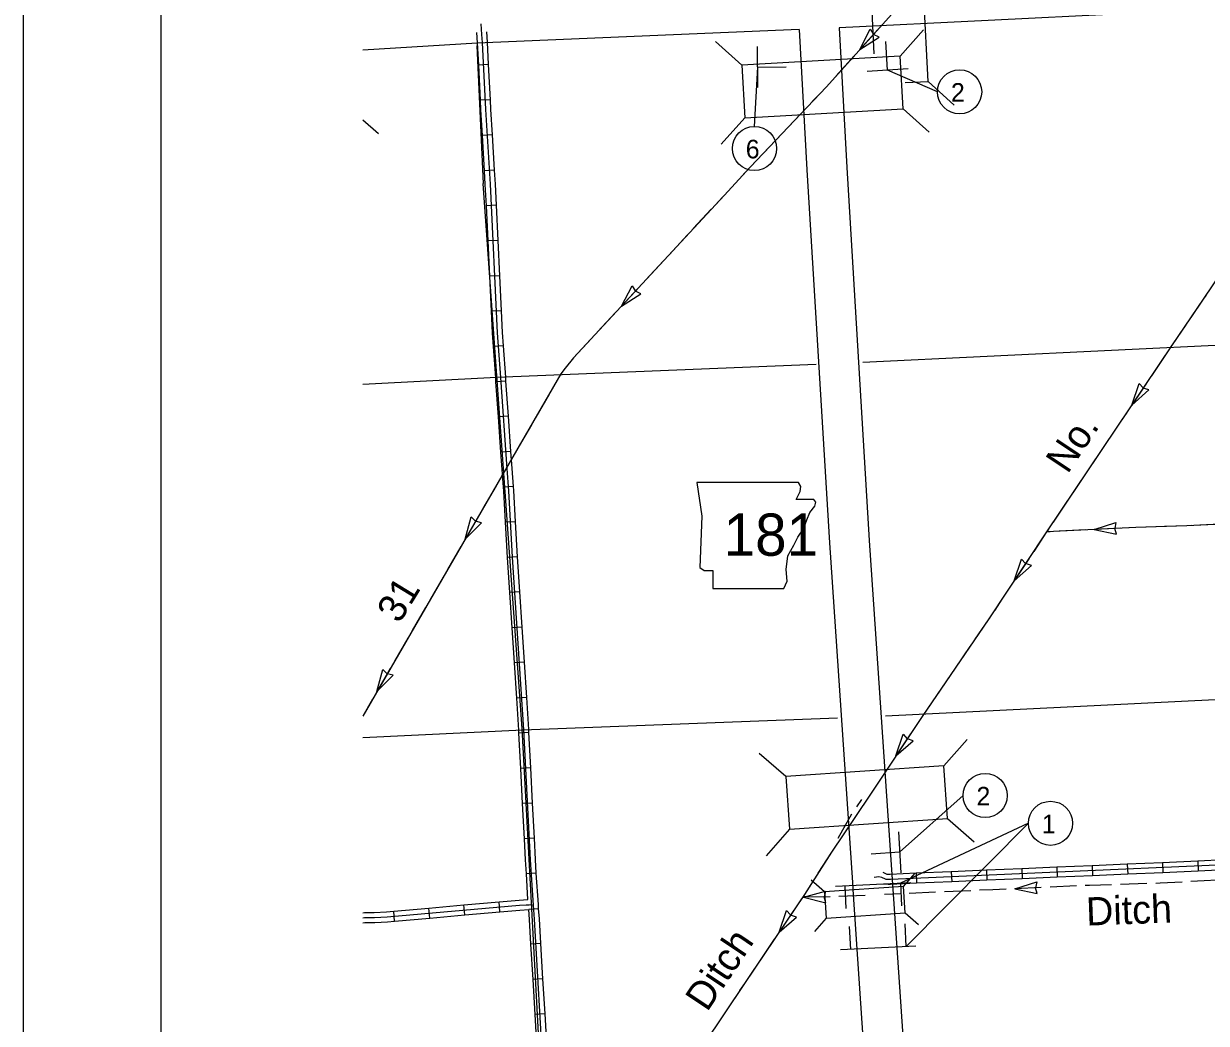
# Model space of a CAD drawing. Extents: x 9792 to 14027, y 9583 to 10649.
# Drawn here: x 9792 to 10326, y 9947 to 10398 of the extents above; entities that cross this region are included whole.
import ezdxf

# ---------------------------------------------------------------- set-up
doc = ezdxf.new("R2010")
doc.units = 0
for name, color, linetype in [('Default', 7, 'Continuous'), ('R_Border', 7, 'Continuous'), ('R_Border Notes', 7, 'Continuous'), ('R_MOT', 7, 'Continuous'), ('R_No Plot', 7, 'Continuous')]:
    doc.layers.add(name, color=color, linetype=linetype)

msp = doc.modelspace()

# ---------------------------------------------------------------- linework, layer by layer
at = {"layer": 'Default'}
for p, q in [((10200.73, 10372.15), (10197.23, 10443.68)), ((10173.39, 10442.51), (10176.22, 10384.58)), ((10169.89, 10386.55), (10174.59, 10395.76)), ((10174.59, 10395.76), (10176.09, 10393.45)), ((10188.07, 10383.64), (10198.67, 10395.51)), ((10116.57, 10379.59), (10104.7, 10390.19)), ((10169.89, 10386.55), (10178.57, 10392.18)), ((10178.57, 10392.18), (10176.12, 10393.43)), ((10002.25, 10379.77), (9997.74, 10379.55)), ((10190.3, 10371.64), (10200.73, 10372.15)), ((10200.73, 10372.15), (10212.52, 10361.46)), ((10003.04, 10363.88), (9998.53, 10363.65)), ((10189.42, 10359.8), (10201.29, 10349.2)), ((9945.36, 10354.85), (9952.44, 10348.59)), ((10117.92, 10355.76), (10107.32, 10343.88)), ((10003.94, 10348.01), (9999.43, 10347.74)), ((10004.89, 10332.12), (10000.38, 10331.85)), ((10005.74, 10316.21), (10001.22, 10315.98)), ((10006.52, 10300.31), (10002, 10300.09)), ((10007.3, 10284.41), (10002.78, 10284.19)), ((10062.2, 10270.68), (10067.04, 10279.83)), ((10067.04, 10279.83), (10068.5, 10277.49)), ((10062.2, 10270.68), (10070.96, 10276.18)), ((10070.96, 10276.18), (10068.53, 10277.47)), ((10008.08, 10268.52), (10003.57, 10268.3)), ((10008.98, 10252.67), (10004.47, 10252.36)), ((10010.08, 10236.8), (10005.56, 10236.49)), ((10292.71, 10225.96), (10296.05, 10235.75)), ((10296.05, 10235.75), (10297.86, 10233.68)), ((10292.71, 10225.96), (10300.5, 10232.77)), ((10300.5, 10232.77), (10297.89, 10233.66)), ((10011.17, 10220.92), (10006.66, 10220.61)), ((10012.27, 10205.04), (10007.76, 10204.73)), ((10013.46, 10189.2), (10008.95, 10188.84)), ((9991.66, 10165.43), (9994.34, 10175.42)), ((9991.66, 10165.43), (9998.98, 10172.73)), ((9994.34, 10175.42), (9996.29, 10173.47)), ((9998.98, 10172.73), (9996.32, 10173.45)), ((10014.42, 10173.26), (10009.9, 10173)), ((10275.76, 10169.73), (10285.6, 10172.92)), ((10285.6, 10172.92), (10285.02, 10170.22)), ((10275.76, 10169.73), (10285.87, 10167.57)), ((10285.87, 10167.57), (10285.03, 10170.19)), ((10015.33, 10157.37), (10010.82, 10157.11)), ((10239.62, 10146.59), (10242.92, 10156.4)), ((10242.92, 10156.4), (10244.74, 10154.33)), ((10239.62, 10146.59), (10247.38, 10153.44)), ((10247.38, 10153.44), (10244.77, 10154.31)), ((10016.36, 10141.51), (10011.85, 10141.21)), ((10017.39, 10125.63), (10012.88, 10125.33)), ((10018.42, 10109.74), (10013.91, 10109.45)), ((9951.81, 10096.55), (9954.49, 10106.54)), ((9951.81, 10096.55), (9959.13, 10103.86)), ((9954.49, 10106.54), (9956.44, 10104.59)), ((9959.13, 10103.86), (9956.47, 10104.57)), ((10019.46, 10093.86), (10014.94, 10093.57)), ((10020.47, 10077.95), (10015.95, 10077.72)), ((10186.2, 10067.44), (10189.52, 10077.24)), ((10189.52, 10077.24), (10191.34, 10075.17)), ((10193.97, 10074.27), (10191.37, 10075.15)), ((10207.91, 10062.95), (10218.38, 10074.93)), ((10186.2, 10067.44), (10193.97, 10074.27)), ((10136.46, 10058.11), (10124.47, 10068.58)), ((10021.28, 10062.05), (10016.76, 10061.83)), ((10022.08, 10046.16), (10017.57, 10045.93)), ((10209.52, 10039.13), (10221.51, 10028.66)), ((10138.07, 10034.29), (10127.6, 10022.31)), ((10022.89, 10030.27), (10018.37, 10030.04)), ((10243, 10016.46), (10243.19, 10011.95)), ((10258.9, 10017.15), (10259.09, 10012.63)), ((10274.8, 10017.84), (10274.99, 10013.32)), ((10290.7, 10018.52), (10290.89, 10014.01)), ((10306.6, 10019.21), (10306.79, 10014.69)), ((10322.5, 10019.9), (10322.69, 10015.38)), ((10023.78, 10014.41), (10019.27, 10014.12)), ((10153.92, 10005.99), (10147.92, 10011.23)), ((10189.64, 10008.4), (10194.88, 10014.4)), ((10195.29, 10014.4), (10195.49, 10009.88)), ((10211.2, 10015.09), (10211.39, 10010.57)), ((10227.1, 10015.78), (10227.29, 10011.26)), ((10144.5, 10003.56), (10154.45, 10006.4)), ((10154.45, 10006.4), (10153.78, 10003.73)), ((10239.91, 10007.44), (10249.77, 10010.56)), ((10239.91, 10007.44), (10250.01, 10005.21)), ((10249.77, 10010.56), (10249.17, 10007.87)), ((10250.01, 10005.21), (10249.18, 10007.84)), ((9991.5, 9995.59), (9991.11, 10000.09)), ((10007.35, 9996.96), (10006.96, 10001.47)), ((10144.5, 10003.56), (10154.53, 10001.05)), ((10154.53, 10001.05), (10153.78, 10003.7)), ((9959.79, 9992.84), (9959.39, 9997.34)), ((9975.64, 9994.21), (9975.25, 9998.72)), ((10024.85, 9998.39), (10020.34, 9998.01)), ((10133.42, 9987.87), (10136.8, 9997.65)), ((10133.42, 9987.87), (10141.24, 9994.65)), ((10136.8, 9997.65), (10138.61, 9995.57)), ((10141.24, 9994.65), (10138.64, 9995.55)), ((10190.45, 9996.5), (10196.44, 9991.26)), ((10154.72, 9994.08), (10149.49, 9988.09)), ((10025.87, 9982.63), (10021.36, 9982.37)), ((10026.79, 9966.74), (10022.28, 9966.48)), ((10027.71, 9950.85), (10023.2, 9950.59))]:
    msp.add_line(p, q, dxfattribs=at)
for points in [[(10317.79, 10544.04), (10315.2, 10541.1), (10291.61, 10516.19), (10289.54, 10513.91), (10277.87, 10501.13), (10255.36, 10478.07), (10209.88, 10430.47), (10186.88, 10405.41), (10154.77, 10369.75), (10120.4, 10333.38)], [(10490.85, 10411.5), (10349.15, 10405.68), (10227.83, 10399.71), (10160.59, 10396.43)], [(10142.52, 10395.6), (9996.99, 10389.46), (9945.36, 10386.24)], [(10003.01, 10325.68), (10001, 10359.42), (9999.49, 10389.8), (9999.21, 10393.44), (9998.89, 10398.17)], [(10142.52, 10395.6), (10145.98, 10332.26)], [(10160.59, 10396.43), (10164.04, 10333.24)], [(10177.88, 10395.42), (10169.89, 10386.55)], [(9997.74, 10379.55), (9997.24, 10389.65), (9996.87, 10394.31)], [(10002.25, 10379.77), (10001.75, 10389.94), (10001.39, 10394.53)], [(9996.88, 10388.27), (9999.81, 10326.08)], [(9998.53, 10363.65), (9997.74, 10379.55)], [(10003.04, 10363.88), (10002.25, 10379.77)], [(10167.23, 10383.59), (10159.24, 10374.72)], [(9999.43, 10347.74), (9998.74, 10359.29), (9998.53, 10363.65)], [(10003.94, 10348.01), (10003.26, 10359.54), (10003.04, 10363.88)], [(10150.97, 10365.73), (10148.43, 10363.04)], [(10145.7, 10360.15), (10137.5, 10351.48)], [(10000.38, 10331.85), (9999.43, 10347.74)], [(10004.89, 10332.12), (10003.94, 10348.01)], [(10134.77, 10348.58), (10126.57, 10339.91)], [(10372.72, 10344.1), (10366.54, 10335.43), (10325.02, 10273.75), (10310.92, 10253.12), (10254.25, 10168.62), (10227.89, 10128.94), (10198.35, 10085.67), (10174.1, 10049.28), (10157.07, 10023.95), (10144.94, 10004.9), (10117.75, 9964.69), (10034.56, 9840.36), (10031.76, 9836.82), (10029.03, 9831.74), (9959.2, 9726.67), (9946.2, 9707.99), (9945.36, 9706.7)], [(10123.84, 10337.02), (10120.4, 10333.38)], [(10120.4, 10333.38), (10108.55, 10320.63), (10040.5, 10247.29), (10036.84, 10242.6), (10034.87, 10240.13), (9945.36, 10085.4)], [(10001.22, 10315.98), (10000.75, 10325.56), (10000.38, 10331.85)], [(10005.74, 10316.21), (10005.27, 10325.8), (10004.89, 10332.12)], [(10120.4, 10333.38), (10116.34, 10329.01)], [(10145.99, 10332.21), (10156.14, 10163.65), (10166.52, 10010.32)], [(10164.04, 10333.29), (10174.19, 10164.81), (10184.56, 10011.54)], [(10034.32, 9769.93), (10026.01, 9919.57), (10017.42, 10079.87), (10005.93, 10239.15), (9999.81, 10326.08)], [(10113.63, 10326.09), (10108.55, 10320.63), (10105.51, 10317.34)], [(10036.84, 9760.09), (10035.83, 9780), (10032.81, 9825.93), (10031.67, 9843.62), (10030.36, 9863.91), (10028.86, 9891.88), (10022.97, 9993.71), (10022.44, 10000.07), (10021.12, 10020.55), (10018.14, 10079.19), (10013.08, 10157.21), (10011.35, 10187.24), (10010.56, 10197.07), (10007.69, 10238.48), (10006.31, 10258.56), (10003.01, 10325.68)], [(10002, 10300.09), (10001.22, 10315.98)], [(10006.52, 10300.31), (10005.74, 10316.21)], [(10102.8, 10314.43), (10094.68, 10305.68)], [(10002.78, 10284.19), (10002, 10300.09)], [(10007.3, 10284.41), (10006.52, 10300.31)], [(10091.97, 10302.76), (10083.86, 10294.01)], [(10081.15, 10291.1), (10073.03, 10282.35)], [(10003.57, 10268.3), (10002.78, 10284.19)], [(10008.08, 10268.52), (10007.3, 10284.41)], [(10070.32, 10279.43), (10062.2, 10270.68)], [(10326.14, 10275.41), (10325.02, 10273.75), (10319.41, 10265.54)], [(10004.47, 10252.36), (10004.05, 10258.43), (10003.57, 10268.3)], [(10008.98, 10252.67), (10008.56, 10258.7), (10008.08, 10268.52)], [(10059.5, 10267.76), (10055.44, 10263.39)], [(10055.44, 10263.39), (10051.38, 10259.01)], [(10317.17, 10262.26), (10310.92, 10253.12), (10310.44, 10252.4)], [(10171.27, 10245.34), (10339.8, 10253.54), (10489.52, 10260.36)], [(10005.56, 10236.49), (10005.44, 10238.32), (10004.47, 10252.36)], [(10010.08, 10236.8), (10009.95, 10238.63), (10008.98, 10252.67)], [(10048.67, 10256.1), (10040.55, 10247.35)], [(10308.22, 10249.1), (10301.57, 10239.18)], [(9945.36, 10235.41), (10005.85, 10238.53), (10150.24, 10244.4)], [(10038.1, 10244.22), (10036.84, 10242.6), (10034.87, 10240.13), (10031.51, 10234.3)], [(10006.66, 10220.61), (10005.56, 10236.49)], [(10011.17, 10220.92), (10010.08, 10236.8)], [(10299.36, 10235.88), (10292.71, 10225.96)], [(10029.51, 10230.86), (10023.54, 10220.53)], [(10007.76, 10204.73), (10006.66, 10220.61)], [(10012.27, 10205.04), (10011.17, 10220.92)], [(10290.49, 10222.66), (10287.17, 10217.7)], [(10021.54, 10217.08), (10015.57, 10206.75)], [(10287.17, 10217.7), (10283.85, 10212.75)], [(10281.63, 10209.44), (10274.98, 10199.53)], [(10008.95, 10188.84), (10008.31, 10196.9), (10007.76, 10204.73)], [(10013.46, 10189.2), (10012.81, 10197.24), (10012.27, 10205.04)], [(10013.57, 10203.31), (10012.52, 10201.49)], [(10008.5, 10194.53), (10007.6, 10192.98)], [(10272.77, 10196.22), (10266.12, 10186.31)], [(10005.6, 10189.53), (10002.61, 10184.37)], [(10009.9, 10173), (10009.09, 10187.08), (10008.95, 10188.84)], [(10014.42, 10173.26), (10013.6, 10187.4), (10013.46, 10189.2)], [(10770.41, 10191.28), (10766.08, 10191.11), (10696.15, 10188.18), (10688.35, 10187.86), (10666.32, 10186.93), (10655.51, 10186.39), (10642.55, 10185.76), (10633.42, 10185.49), (10616.02, 10184.62), (10606.1, 10184.18), (10598.03, 10183.88), (10591.77, 10183.75), (10431.46, 10176.05), (10431.46, 10176.02), (10377.39, 10174.22), (10317.58, 10171.38), (10294.5, 10170.7), (10254.25, 10168.62)], [(10002.61, 10184.37), (9999.63, 10179.2)], [(10263.9, 10183.01), (10257.25, 10173.09)], [(9997.63, 10175.76), (9991.66, 10165.43)], [(10010.82, 10157.11), (10009.9, 10173)], [(10015.33, 10157.37), (10014.42, 10173.26)], [(10303.58, 10170.96), (10294.5, 10170.7), (10291.65, 10170.55)], [(10319.49, 10171.47), (10317.58, 10171.38), (10307.56, 10171.08)], [(10335.38, 10172.22), (10323.46, 10171.66)], [(10255.04, 10169.79), (10254.25, 10168.62), (10248.43, 10159.85)], [(10255.89, 10168.71), (10254.25, 10168.62)], [(10271.78, 10169.53), (10259.86, 10168.91)], [(10287.68, 10170.34), (10275.76, 10169.73)], [(9989.66, 10161.98), (9983.69, 10151.65)], [(10011.85, 10141.21), (10010.82, 10157.07), (10010.82, 10157.11)], [(10016.36, 10141.51), (10015.33, 10157.35), (10015.33, 10157.37)], [(10246.22, 10156.54), (10239.62, 10146.59)], [(9981.69, 10148.21), (9975.72, 10137.87)], [(10012.88, 10125.33), (10011.85, 10141.21)], [(10017.39, 10125.63), (10016.36, 10141.51)], [(10237.42, 10143.28), (10234.11, 10138.31)], [(9973.72, 10134.43), (9967.75, 10124.1)], [(10234.11, 10138.31), (10230.81, 10133.34)], [(10228.61, 10130.02), (10227.89, 10128.94), (10221.89, 10120.16)], [(10013.91, 10109.45), (10012.88, 10125.33)], [(10018.42, 10109.74), (10017.39, 10125.63)], [(9965.75, 10120.66), (9959.78, 10110.32)], [(10219.65, 10116.87), (10212.92, 10107.01)], [(9957.78, 10106.88), (9954.79, 10101.71)], [(10014.94, 10093.57), (10013.91, 10109.45)], [(10019.46, 10093.86), (10018.42, 10109.74)], [(9954.79, 10101.71), (9951.81, 10096.55)], [(10210.68, 10103.73), (10203.95, 10093.87)], [(9949.81, 10093.1), (9945.36, 10085.4)], [(10015.95, 10077.72), (10015.89, 10079.06), (10014.94, 10093.57)], [(10020.47, 10077.95), (10020.4, 10079.32), (10019.46, 10093.86)], [(10181.46, 10085.62), (10348.54, 10093.79), (10363.71, 10094.39)], [(10201.71, 10090.58), (10198.35, 10085.67), (10195.03, 10080.69)], [(9945.36, 10075.69), (10017.76, 10079.22), (10159.81, 10084.68)], [(10016.76, 10061.83), (10015.95, 10077.72)], [(10021.28, 10062.05), (10020.47, 10077.95)], [(10192.82, 10077.38), (10186.2, 10067.44)], [(10184, 10064.13), (10180.69, 10059.17)], [(10017.57, 10045.93), (10016.76, 10061.83)], [(10022.08, 10046.16), (10021.28, 10062.05)], [(10180.69, 10059.17), (10177.38, 10054.2)], [(10018.37, 10030.04), (10017.57, 10045.93)], [(10022.89, 10030.27), (10022.08, 10046.16)], [(10170.58, 10047.77), (10168.37, 10044.48)], [(10166.08, 10041.1), (10159.95, 10030.2)], [(10019.27, 10014.12), (10018.86, 10020.42), (10018.37, 10030.04)], [(10023.78, 10014.41), (10023.38, 10020.68), (10022.89, 10030.27)], [(10157.42, 10024.47), (10157.07, 10023.95), (10151, 10014.41)], [(10354.38, 10019.32), (10334.6, 10018.16), (10183.72, 10011.64), (10182.72, 10011.64), (10181.82, 10011.67), (10181.53, 10011.75), (10179.87, 10012.51), (10178.52, 10012.8), (10177.41, 10012.73), (10176.32, 10012.54)], [(10243, 10016.46), (10227.1, 10015.78)], [(10258.9, 10017.15), (10243, 10016.46)], [(10274.8, 10017.84), (10258.9, 10017.15)], [(10290.7, 10018.52), (10274.8, 10017.84)], [(10306.6, 10019.21), (10290.7, 10018.52)], [(10322.5, 10019.9), (10306.6, 10019.21)], [(10338.36, 10020.64), (10334.48, 10020.42), (10322.5, 10019.9)], [(10338.62, 10016.13), (10334.71, 10015.9), (10322.69, 10015.38)], [(10020.02, 10002.52), (10019.27, 10014.12)], [(10024.83, 9998.57), (10024.69, 10000.24), (10023.78, 10014.41)], [(10148.86, 10011.05), (10144.94, 10004.9), (10142.34, 10001.05)], [(10195.29, 10014.4), (10183.67, 10013.9), (10182.76, 10013.9), (10182.24, 10013.92), (10180.37, 10014.78)], [(10184.57, 10011.54), (10186.65, 9980.73)], [(10211.2, 10015.09), (10195.29, 10014.4)], [(10227.1, 10015.78), (10211.2, 10015.09)], [(10227.29, 10011.26), (10211.39, 10010.57)], [(10243.19, 10011.95), (10227.29, 10011.26)], [(10259.09, 10012.63), (10243.19, 10011.95)], [(10274.99, 10013.32), (10259.09, 10012.63)], [(10290.89, 10014.01), (10274.99, 10013.32)], [(10306.79, 10014.69), (10290.89, 10014.01)], [(10322.69, 10015.38), (10306.79, 10014.69)], [(10325.37, 10010.94), (10319.41, 10010.63)], [(10331.33, 10011.24), (10325.37, 10010.94)], [(10166.52, 10010.32), (10166.74, 10007.14), (10168.56, 9980.14)], [(10195.49, 10009.88), (10183.77, 10009.38), (10182.68, 10009.38), (10180.72, 10009.45)], [(10204.13, 10005.84), (10192.21, 10005.31)], [(10211.39, 10010.57), (10195.49, 10009.88)], [(10220.03, 10006.55), (10208.11, 10006.02)], [(10229.97, 10007), (10224.01, 10006.73)], [(10235.93, 10007.26), (10229.97, 10007)], [(10251.83, 10007.97), (10239.91, 10007.44)], [(10267.73, 10008.68), (10255.8, 10008.15)], [(10283.63, 10009.25), (10273.65, 10008.95), (10271.7, 10008.86)], [(10299.54, 10009.73), (10287.61, 10009.37)], [(10315.44, 10010.42), (10305.62, 10009.92), (10303.52, 10009.85)], [(9945.36, 9994.35), (9946.22, 9994.39), (9950.69, 9994.49), (9956.34, 9994.81), (10016.13, 9999.99), (10019.22, 10000.2), (10020.59, 10000.23), (10021.36, 10000.26), (10021.94, 10000.18), (10022.44, 10000.07)], [(9975.25, 9998.72), (9991.11, 10000.09)], [(9991.11, 10000.09), (10006.96, 10001.47)], [(10006.96, 10001.47), (10015.96, 10002.25), (10020.02, 10002.52)], [(10156.43, 10003.76), (10146.56, 10003.59), (10144.94, 10003.98)], [(10172.33, 10004.42), (10160.41, 10003.89)], [(10188.23, 10005.13), (10181.02, 10004.81)], [(9945.36, 9996.61), (9946.15, 9996.65), (9950.6, 9996.75), (9956.18, 9997.06), (9959.39, 9997.34)], [(9959.39, 9997.34), (9975.25, 9998.72)], [(9975.64, 9994.21), (9991.5, 9995.59)], [(9991.5, 9995.59), (10007.35, 9996.96)], [(10007.35, 9996.96), (10016.31, 9997.74), (10020.34, 9998.01)], [(10021.36, 9982.37), (10020.71, 9993.55), (10020.34, 9998.01)], [(10025.87, 9982.63), (10025.22, 9993.87), (10024.83, 9998.57)], [(10140.11, 9997.76), (10133.42, 9987.87)], [(9945.36, 9992.09), (9946.3, 9992.13), (9950.78, 9992.23), (9956.5, 9992.55), (9959.79, 9992.84)], [(9959.79, 9992.84), (9975.64, 9994.21)], [(10131.2, 9984.58), (10127.85, 9979.63)], [(10022.28, 9966.48), (10021.36, 9982.37)], [(10026.79, 9966.74), (10025.87, 9982.63)], [(10127.85, 9979.63), (10124.51, 9974.69)], [(10168.56, 9980.14), (10176.81, 9857.92), (10182.05, 9776.37)], [(10186.65, 9980.73), (10194.86, 9859.1), (10200.19, 9776.13)], [(10122.28, 9971.39), (10117.75, 9964.69), (10115.61, 9961.49)], [(10023.2, 9950.59), (10022.28, 9966.48)], [(10027.71, 9950.85), (10026.79, 9966.74)], [(10113.4, 9958.19), (10106.76, 9948.27)], [(10024.12, 9934.71), (10023.2, 9950.59)], [(10028.63, 9934.97), (10027.71, 9950.85)]]:
    msp.add_lwpolyline(points, dxfattribs=at)
for points in [[(10117.92, 10355.76), (10189.42, 10359.8), (10188.07, 10383.64), (10116.57, 10379.59)], [(10096.29, 10191), (10098.59, 10175.7), (10097.57, 10152.5), (10099.61, 10151.22), (10103.43, 10151.22), (10103.43, 10143.06), (10135.56, 10143.06), (10137.09, 10146.38), (10136.58, 10151.73), (10137.35, 10157.85), (10140.15, 10162.69), (10141.93, 10166.26), (10144.48, 10170.09), (10146.01, 10174.17), (10147.29, 10177.48), (10149.58, 10180.29), (10150.09, 10182.07), (10149.07, 10183.35), (10141.17, 10183.35), (10142.95, 10186.92), (10143.21, 10189.21), (10142.15, 10190.97)], [(10207.91, 10062.95), (10136.46, 10058.11), (10138.07, 10034.29), (10209.52, 10039.13)], [(10189.64, 10008.4), (10153.92, 10005.99), (10154.72, 9994.08), (10190.45, 9996.5)]]:
    msp.add_lwpolyline(points, close=True, dxfattribs=at)
at = {"layer": 'R_Border'}
msp.add_line((9854.26, 9602.55), (9854.26, 10629.85), dxfattribs=at)
at = {"layer": 'R_Border Notes'}
for p, q in [((10122.29, 10351.86), (10123.78, 10378.67)), ((10205, 10367.49), (10182.47, 10377.27)), ((10216.53, 10049.52), (10187.88, 10023.89)), ((10246.06, 10037), (10188.24, 10010.02)), ((10246.06, 10037), (10190.9, 9981.29))]:
    msp.add_line(p, q, dxfattribs=at)
for centre in [(10214.97, 10367.49), (10122.29, 10341.89), (10226.51, 10049.52), (10256.03, 10037)]:
    msp.add_circle(centre, 9.97, dxfattribs=at)
at = {"layer": 'R_MOT'}
for p, q in [((10182.47, 10377.27), (10181.69, 10390.17)), ((10123.83, 10369.45), (10123.74, 10387.98)), ((10123.78, 10378.67), (10136.7, 10378.73)), ((10191.68, 10377.84), (10173.18, 10376.7)), ((10187.31, 10033.09), (10188.45, 10014.6)), ((10187.88, 10023.89), (10174.99, 10023.1)), ((10158.84, 10008.58), (10192.88, 10010.25)), ((10163.14, 10008.79), (10163.65, 9998.48)), ((10188.24, 10010.02), (10188.74, 9999.72)), ((10165.8, 9980.05), (10165.29, 9990.36)), ((10190.9, 9981.29), (10190.39, 9991.6)), ((10195.19, 9981.5), (10161.16, 9979.82))]:
    msp.add_line(p, q, dxfattribs=at)
at = {"layer": 'R_No Plot'}
for points in [[(9792.23, 10649.32), (11458.93, 10649.32), (11458.93, 9582.63), (9792.23, 9582.63)], [(11023.86, 10629.85), (11023.86, 10580.45), (11202.52, 10580.45), (11202.52, 10565.85), (11318.52, 10565.85), (11318.52, 10444.19), (11435.16, 10444.19), (11435.16, 9602.55), (9854.26, 9602.55), (9854.26, 10629.85)]]:
    msp.add_lwpolyline(points, close=True, dxfattribs=at)

# ---------------------------------------------------------------- texts
at = {"layer": 'Default'}
for s, rotation, p in [('No.', 56.1528, (10263.71, 10194.46)), ('31', 58.5548, (9961.9, 10126.83)), ('Ditch', 2.1104, (10272.31, 9990.76)), ('Ditch', 56.1413, (10100.89, 9951.43))]:
    msp.add_text(s, height=12.732, rotation=rotation, dxfattribs=at).set_placement(p)
msp.add_text('181', height=19.098, dxfattribs=at).set_placement((10108.41, 10157.87))
at = {"layer": 'R_Border Notes'}
for s, p in [('2', (10211.05, 10363.01)), ('6', (10118.37, 10337.41)), ('2', (10222.59, 10045.04)), ('1', (10252.11, 10032.52))]:
    msp.add_text(s, height=8.4, dxfattribs=at).set_placement(p)

doc.saveas('drawing.dxf')
